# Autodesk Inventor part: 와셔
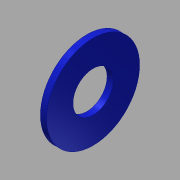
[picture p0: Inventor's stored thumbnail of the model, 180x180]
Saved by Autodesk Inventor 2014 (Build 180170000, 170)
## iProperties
Created: 2015-12
Part Number: 와셔
Material: 스테인리스강
Document SubType Name: Modeling
Designer: mduedu
Density: 8.08 g/cm^3
Appearance: 파란색 - 벽 페인트 - 광택
Author: mduedu
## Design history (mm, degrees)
sketch "스케치1"
  geometry: C1 r 3.25 at (0, 0); C2 r 7.5 at (0, 0); 1 further point
  constraints: 2 centre point, 2 coincident
  dimensions: "d0" = 6.5 diameter of C1; "d1" = 15 diameter of C2
extrude "돌출1" new body sketch "스케치1" stored distance "d2" = 1; taper "d3" = 0 deg
node "솔리드1"
